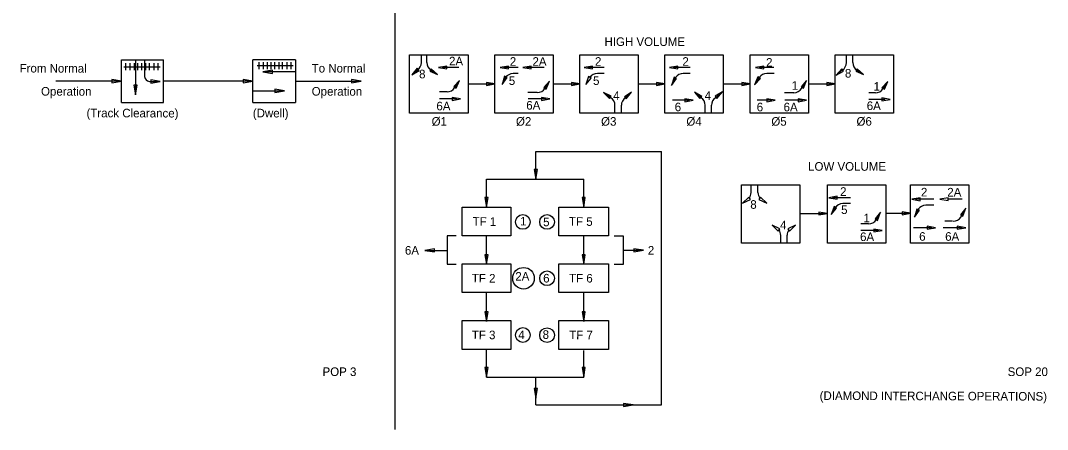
# Model space of a CAD drawing. Extents: x 10027 to 10797, y 10033 to 10528.
# Drawn here: x 10347 to 10765.1, y 10033.4 to 10199.9 of the extents above; entities that cross this region are included whole.
import ezdxf

# ---------------------------------------------------------------- set-up
doc = ezdxf.new("R2010")
doc.units = 0
for name, color, linetype in [('AdhocPoint_dp', 7, 'Continuous'), ('Default', 7, 'Continuous'), ('Dimension', 7, 'Continuous'), ('DSIndex', 7, 'Continuous'), ('SupstrConc', 7, 'Continuous')]:
    doc.layers.add(name, color=color, linetype=linetype)

msp = doc.modelspace()

# ---------------------------------------------------------------- linework, layer by layer
at = {"layer": 'AdhocPoint_dp'}
msp.add_line((10499.47, 10033.43), (10499.47, 10528.43), dxfattribs=at)
at = {"layer": 'Default'}
for p, q in [((10510.17, 10182.8), (10510.17, 10185.91)), ((10512.33, 10182.8), (10512.33, 10185.91)), ((10683.2, 10182.75), (10683.2, 10185.9)), ((10685.82, 10182.75), (10685.82, 10185.91)), ((10388.02, 10166.55), (10388.02, 10183.94)), ((10388.02, 10183.94), (10405.14, 10183.94)), ((10389.89, 10179.66), (10389.89, 10182.56)), ((10391.65, 10179.66), (10391.65, 10182.56)), ((10393.33, 10179.66), (10393.33, 10182.56)), ((10393.81, 10183.94), (10393.81, 10169.64)), ((10394.77, 10179.66), (10394.77, 10182.56)), ((10396.33, 10179.66), (10396.33, 10182.56)), ((10397.45, 10183.94), (10397.45, 10177.04)), ((10397.99, 10179.66), (10397.99, 10182.56)), ((10399.43, 10179.66), (10399.43, 10182.56)), ((10401.31, 10179.66), (10401.31, 10182.56)), ((10402.98, 10179.66), (10402.98, 10182.56)), ((10405.14, 10166.55), (10405.14, 10183.94)), ((10458.95, 10183.94), (10441.55, 10183.94)), ((10441.55, 10166.55), (10441.55, 10183.94)), ((10443.28, 10181.53), (10457.98, 10181.53)), ((10444.12, 10180.11), (10444.12, 10183)), ((10445.88, 10180.11), (10445.88, 10183)), ((10447.55, 10180.11), (10447.55, 10183)), ((10449, 10180.11), (10449, 10183)), ((10450.56, 10180.11), (10450.56, 10183)), ((10452.21, 10180.11), (10452.21, 10183)), ((10453.66, 10180.11), (10453.66, 10183)), ((10455.54, 10180.11), (10455.54, 10183)), ((10457.21, 10180.11), (10457.21, 10183)), ((10458.95, 10183.94), (10458.95, 10166.55)), ((10389.05, 10181.09), (10403.75, 10181.09)), ((10458.92, 10179.04), (10445.59, 10179.04)), ((10525.44, 10180.74), (10518.6, 10180.74)), ((10549.62, 10180.74), (10543.66, 10180.74)), ((10549.55, 10178.29), (10547.5, 10178.29)), ((10560.21, 10180.75), (10552.88, 10180.75)), ((10584.6, 10180.75), (10577.86, 10180.75)), ((10584.6, 10178.32), (10581.83, 10178.32)), ((10619.55, 10180.75), (10612.68, 10180.75)), ((10653.68, 10180.75), (10647.67, 10180.75)), ((10388.02, 10175.24), (10361.28, 10175.24)), ((10399.41, 10175.07), (10403.85, 10175.07)), ((10441.55, 10175.24), (10405.14, 10175.24)), ((10458.95, 10175.24), (10485.64, 10175.24)), ((10529.15, 10174.06), (10540.04, 10174.06)), ((10563.8, 10174.06), (10574.7, 10174.06)), ((10598.46, 10174.06), (10609.35, 10174.06)), ((10633.11, 10174.06), (10644.01, 10174.06)), ((10667.77, 10174.06), (10678.66, 10174.06)), ((10441.55, 10171.21), (10454.37, 10171.21)), ((10661.84, 10170.51), (10658.06, 10170.51)), ((10695.01, 10170.46), (10692.39, 10170.46)), ((10388.02, 10166.55), (10405.14, 10166.55)), ((10441.55, 10166.55), (10458.95, 10166.55)), ((10524.65, 10167.97), (10517.59, 10167.97)), ((10561, 10167.97), (10553.6, 10167.97)), ((10588.98, 10162.22), (10588.98, 10165.37)), ((10591.6, 10162.22), (10591.6, 10165.37)), ((10618.31, 10167.41), (10612.36, 10167.41)), ((10625.7, 10162.22), (10625.7, 10165.37)), ((10628.32, 10162.22), (10628.32, 10165.37)), ((10652.81, 10167.41), (10646.85, 10167.41)), ((10665.49, 10167.4), (10658.13, 10167.4)), ((10698.97, 10167.8), (10692.4, 10167.8)), ((10556.73, 10135.27), (10556.73, 10146.6)), ((10556.73, 10146.6), (10607.88, 10146.6)), ((10607.88, 10043.39), (10607.88, 10146.6)), ((10536.7, 10135.27), (10576.25, 10135.27)), ((10536.7, 10123.95), (10536.7, 10135.27)), ((10576.25, 10123.95), (10576.25, 10135.27)), ((10644.42, 10129.83), (10644.42, 10132.99)), ((10647.22, 10129.82), (10647.22, 10132.98)), ((10684.92, 10127.77), (10677.52, 10127.77)), ((10684.91, 10125.35), (10681.75, 10125.35)), ((10718.76, 10127.11), (10711.31, 10127.11)), ((10730.34, 10127.12), (10724.39, 10127.12)), ((10664.31, 10121.34), (10675.46, 10121.34)), ((10699.22, 10121.41), (10709.34, 10121.41)), ((10692.24, 10117.09), (10689.08, 10117.09)), ((10718, 10115.54), (10710.56, 10115.54)), ((10730.34, 10115.54), (10722.67, 10115.54)), ((10536.7, 10100.87), (10536.7, 10112.19)), ((10576.25, 10100.87), (10576.25, 10112.19)), ((10656.49, 10109.28), (10656.49, 10112.44)), ((10659.09, 10109.29), (10659.09, 10112.45)), ((10696.37, 10114.42), (10689.11, 10114.42)), ((10511.58, 10106.33), (10520.63, 10106.33)), ((10592.36, 10106.35), (10600.59, 10106.35)), ((10536.7, 10077.79), (10536.7, 10089.11)), ((10576.25, 10077.79), (10576.25, 10089.11)), ((10536.7, 10054.71), (10536.7, 10066.03)), ((10576.25, 10054.71), (10576.25, 10065.6)), ((10536.7, 10054.71), (10576.25, 10054.71)), ((10556.73, 10043.39), (10556.73, 10054.71)), ((10556.73, 10043.39), (10607.88, 10043.39))]:
    msp.add_line(p, q, dxfattribs=at)
for centre, radius, start, end in [((10506.39, 10182.82), 3.78, 304.2835, 359.6758), ((10516.12, 10182.83), 3.78, 180.3242, 235.7165), ((10679.43, 10182.77), 3.78, 304.2835, 359.6758), ((10689.6, 10182.77), 3.78, 180.3242, 235.7165), ((10547.52, 10174.51), 3.78, 90.3242, 145.7165), ((10581.84, 10174.54), 3.78, 90.3242, 145.7165), ((10399.61, 10177.23), 2.17, 185.1228, 264.5013), ((10661.82, 10174.29), 3.78, 270.3242, 325.7165), ((10695, 10174.25), 3.78, 270.3242, 325.7165), ((10585.21, 10165.36), 3.78, 0.3242, 55.7165), ((10595.38, 10165.35), 3.78, 124.2835, 179.6758), ((10621.92, 10165.36), 3.78, 0.3242, 55.7165), ((10632.1, 10165.36), 3.78, 124.2835, 179.6758), ((10640.64, 10129.85), 3.78, 323.8272, 359.6758), ((10650.99, 10129.84), 3.78, 180.3242, 217.1963), ((10681.78, 10121.57), 3.78, 90.3242, 145.7165), ((10692.22, 10120.87), 3.78, 270.3242, 325.7165), ((10652.71, 10112.42), 3.78, 0.3242, 35.4148), ((10662.87, 10112.44), 3.78, 145.5087, 179.6758)]:
    msp.add_arc(centre, radius, start, end, dxfattribs=at)
at = {"layer": 'Dimension'}
for p, q in [((10508.52, 10179.7), (10507.37, 10178.75)), ((10513.99, 10179.71), (10515.54, 10178.75)), ((10619.63, 10178.34), (10616.86, 10178.34)), ((10653.76, 10178.33), (10650.99, 10178.33)), ((10681.55, 10179.64), (10680.2, 10178.57)), ((10687.47, 10179.65), (10689.02, 10178.66)), ((10523.71, 10172.51), (10524.9, 10174.25)), ((10544.4, 10176.64), (10543.69, 10175.16)), ((10560.49, 10172.24), (10561.59, 10173.92)), ((10613.7, 10176.68), (10612.71, 10174.87)), ((10647.75, 10176.68), (10646.66, 10174.97)), ((10664.94, 10172.17), (10666.14, 10174.09)), ((10698.13, 10172.12), (10699.25, 10173.87)), ((10520.61, 10170.86), (10517.6, 10170.86)), ((10557.32, 10170.59), (10553.54, 10170.59)), ((10587.33, 10168.48), (10585.58, 10169.7)), ((10593.25, 10168.47), (10594.67, 10169.77)), ((10624.05, 10168.48), (10622.48, 10169.84)), ((10629.97, 10168.48), (10631.63, 10169.88)), ((10618.31, 10167.41), (10619.34, 10167.41)), ((10678.66, 10123.69), (10677.77, 10122.16)), ((10712.48, 10123.04), (10711.61, 10121.15)), ((10718.77, 10124.69), (10715.62, 10124.69)), ((10695.34, 10118.74), (10696.34, 10120.54)), ((10729.81, 10119.86), (10731.08, 10122.12)), ((10726.46, 10118.21), (10723.31, 10118.21))]:
    msp.add_line(p, q, dxfattribs=at)
for centre, radius in [((10551.47, 10117.91), 3), ((10561.35, 10117.91), 3), ((10551.76, 10094.98), 4.39), ((10561.36, 10094.96), 3), ((10551.49, 10071.87), 3), ((10561.36, 10071.81), 3)]:
    msp.add_circle(centre, radius, dxfattribs=at)
for centre, start, end in [((10616.82, 10174.56), 90.3242, 145.7165), ((10650.87, 10174.55), 90.3242, 145.7165), ((10520.59, 10174.64), 270.3242, 325.7165), ((10557.37, 10174.37), 270.3242, 325.7165), ((10715.61, 10120.91), 90.3242, 145.7165), ((10726.69, 10121.99), 270.3242, 325.7165)]:
    msp.add_arc(centre, 3.78, start, end, dxfattribs=at)
at = {"layer": 'DSIndex'}
for points in [[(10505.39, 10185.91), (10529.15, 10185.91), (10529.15, 10162.22), (10505.39, 10162.22)], [(10540.04, 10185.91), (10563.8, 10185.91), (10563.8, 10162.22), (10540.04, 10162.22)], [(10574.7, 10185.91), (10598.46, 10185.91), (10598.46, 10162.22), (10574.7, 10162.22)], [(10609.35, 10185.91), (10633.11, 10185.91), (10633.11, 10162.22), (10609.35, 10162.22)], [(10644.01, 10185.91), (10667.77, 10185.91), (10667.77, 10162.22), (10644.01, 10162.22)], [(10678.66, 10185.91), (10702.42, 10185.91), (10702.42, 10162.22), (10678.66, 10162.22)], [(10640.55, 10132.99), (10664.31, 10132.99), (10664.31, 10109.29), (10640.55, 10109.29)], [(10675.46, 10132.99), (10699.22, 10132.99), (10699.22, 10109.29), (10675.46, 10109.29)], [(10709.34, 10132.99), (10733.1, 10132.99), (10733.1, 10109.29), (10709.34, 10109.29)], [(10526.8, 10123.95), (10546.54, 10123.95), (10546.54, 10112.19), (10526.8, 10112.19)], [(10566.15, 10123.95), (10586.34, 10123.95), (10586.34, 10112.19), (10566.15, 10112.19)], [(10526.8, 10100.87), (10546.54, 10100.87), (10546.54, 10089.11), (10526.8, 10089.11)], [(10566.15, 10100.87), (10586.34, 10100.87), (10586.34, 10089.11), (10566.15, 10089.11)], [(10526.8, 10077.79), (10546.54, 10077.79), (10546.54, 10066.03), (10526.8, 10066.03)], [(10566.15, 10077.79), (10586.34, 10077.79), (10586.34, 10066.03), (10566.15, 10066.03)]]:
    msp.add_lwpolyline(points, close=True, dxfattribs=at)
for points in [[(10524.31, 10112.19), (10520.7, 10112.19), (10520.7, 10100.66), (10524.31, 10100.66)], [(10588.67, 10112.18), (10592.28, 10112.18), (10592.28, 10100.57), (10588.67, 10100.57)]]:
    msp.add_lwpolyline(points, dxfattribs=at)
at = {"layer": 'SupstrConc'}
for points in [[(10445.59, 10179.04), (10449.5, 10178.38), (10449.5, 10179.7)], [(10506.25, 10177.81), (10509.25, 10179.55), (10508.51, 10180.44)], [(10516.78, 10177.98), (10514.18, 10180.27), (10513.57, 10179.28)], [(10517.14, 10180.74), (10520.55, 10180.16), (10520.55, 10181.32)], [(10542.19, 10180.74), (10545.61, 10180.16), (10545.61, 10181.32)], [(10551.41, 10180.75), (10554.83, 10180.17), (10554.83, 10181.33)], [(10576.44, 10180.75), (10579.85, 10180.18), (10579.85, 10181.33)], [(10611.22, 10180.75), (10614.63, 10180.17), (10614.63, 10181.33)], [(10646.2, 10180.75), (10649.62, 10180.17), (10649.62, 10181.33)], [(10679.05, 10177.66), (10682.09, 10179.33), (10681.37, 10180.24)], [(10690.19, 10177.91), (10687.62, 10180.24), (10687, 10179.27)], [(10388.02, 10175.24), (10384.11, 10175.91), (10384.11, 10174.58)], [(10393.81, 10169.64), (10394.47, 10173.54), (10393.15, 10173.54)], [(10403.85, 10175.07), (10399.94, 10175.73), (10399.94, 10174.41)], [(10441.55, 10175.24), (10437.65, 10175.91), (10437.65, 10174.58)], [(10485.64, 10175.24), (10481.74, 10175.91), (10481.74, 10174.58)], [(10525.73, 10175.46), (10523.32, 10172.97), (10524.28, 10172.31)], [(10540.04, 10174.06), (10536.63, 10174.64), (10536.63, 10173.48)], [(10543.06, 10173.83), (10545.05, 10176.67), (10544.01, 10177.17)], [(10562.4, 10175.17), (10560.05, 10172.63), (10561.02, 10171.99)], [(10574.7, 10174.06), (10571.28, 10174.64), (10571.28, 10173.48)], [(10577.09, 10173.8), (10579.28, 10176.49), (10578.28, 10177.06)], [(10609.35, 10174.06), (10605.94, 10174.64), (10605.94, 10173.48)], [(10611.97, 10173.5), (10614.11, 10176.23), (10613.1, 10176.78)], [(10644.01, 10174.06), (10640.59, 10174.64), (10640.59, 10173.48)], [(10645.87, 10173.74), (10648.2, 10176.3), (10647.22, 10176.92)], [(10667.04, 10175.54), (10664.74, 10172.94), (10665.72, 10172.33)], [(10678.66, 10174.06), (10675.24, 10174.64), (10675.24, 10173.48)], [(10700.05, 10175.1), (10697.71, 10172.54), (10698.68, 10171.92)], [(10454.37, 10171.21), (10450.46, 10171.88), (10450.46, 10170.55)], [(10584.27, 10170.62), (10586.74, 10168.19), (10587.4, 10169.13)], [(10595.74, 10170.74), (10592.82, 10168.87), (10593.6, 10168.01)], [(10621.41, 10170.76), (10623.61, 10168.08), (10624.37, 10168.96)], [(10632.75, 10170.81), (10629.76, 10169.06), (10630.5, 10168.18)], [(10526.11, 10167.97), (10522.7, 10168.55), (10522.7, 10167.39)], [(10562.47, 10167.96), (10559.06, 10168.54), (10559.06, 10167.39)], [(10620.81, 10167.41), (10617.39, 10167.99), (10617.39, 10166.83)], [(10654.27, 10167.41), (10650.86, 10167.99), (10650.86, 10166.83)], [(10666.95, 10167.4), (10663.54, 10167.98), (10663.54, 10166.82)], [(10701.09, 10167.8), (10697.67, 10168.37), (10697.67, 10167.22)], [(10556.73, 10135.27), (10557.39, 10139.18), (10556.06, 10139.18)], [(10536.7, 10123.95), (10537.36, 10127.85), (10536.04, 10127.85)], [(10576.25, 10123.95), (10576.92, 10127.85), (10575.59, 10127.85)], [(10640.96, 10125.57), (10644.11, 10127.01), (10643.46, 10127.97)], [(10650.78, 10125.59), (10648.28, 10128), (10647.63, 10127.04)], [(10676.06, 10127.77), (10679.48, 10127.19), (10679.48, 10128.35)], [(10709.85, 10127.11), (10713.26, 10126.53), (10713.26, 10127.69)], [(10721.21, 10127.15), (10724.63, 10126.58), (10724.63, 10127.73)], [(10676.98, 10120.89), (10679.2, 10123.56), (10678.2, 10124.14)], [(10711, 10119.82), (10712.96, 10122.68), (10711.91, 10123.16)], [(10731.82, 10123.49), (10729.65, 10120.79), (10730.66, 10120.23)], [(10675.46, 10121.34), (10672.04, 10121.92), (10672.04, 10120.76)], [(10697.06, 10121.81), (10694.88, 10119.12), (10695.89, 10118.55)], [(10709.34, 10121.41), (10705.92, 10121.99), (10705.92, 10120.83)], [(10652.99, 10116.57), (10655.49, 10114.17), (10656.14, 10115.12)], [(10662.55, 10116.55), (10659.4, 10115.1), (10660.05, 10114.15)], [(10697.84, 10114.42), (10694.42, 10115), (10694.42, 10113.84)], [(10719.47, 10115.54), (10716.05, 10116.12), (10716.05, 10114.96)], [(10731.8, 10115.54), (10728.39, 10116.12), (10728.39, 10114.96)], [(10511.58, 10106.33), (10515.48, 10105.67), (10515.48, 10106.99)], [(10600.59, 10106.35), (10596.69, 10107.01), (10596.69, 10105.69)], [(10536.7, 10100.66), (10537.36, 10104.56), (10536.04, 10104.56)], [(10576.25, 10100.66), (10576.92, 10104.56), (10575.59, 10104.56)], [(10536.7, 10077.36), (10537.36, 10081.26), (10536.04, 10081.26)], [(10576.25, 10077.36), (10576.92, 10081.26), (10575.59, 10081.26)], [(10536.7, 10054.71), (10537.36, 10058.61), (10536.04, 10058.61)], [(10576.25, 10054.71), (10576.92, 10058.61), (10575.59, 10058.61)], [(10556.73, 10046.15), (10557.39, 10050.06), (10556.06, 10050.06)], [(10596.34, 10043.39), (10592.44, 10044.05), (10592.44, 10042.72)]]:
    msp.add_lwpolyline(points, close=True, dxfattribs=at)

# ---------------------------------------------------------------- texts
at = {"layer": 'Dimension'}
for s, p in [('HIGH VOLUME', (10584.73, 10189.53)), ('2A', (10521.43, 10181.61)), ('2', (10546.18, 10181.46)), ('2A', (10555.41, 10181.46)), ('2', (10580.85, 10181.46)), ('2', (10616.44, 10181.45)), ('2', (10650.52, 10181.1)), ('8', (10509.23, 10176.35)), ('8', (10682.63, 10176.67)), ('5', (10545.75, 10173.66)), ('5', (10580.06, 10173.66)), ('1', (10660.94, 10171.69)), ('1', (10694.3, 10171.32)), ('4', (10588.26, 10167.59)), ('4', (10625.51, 10167.59)), ('6A', (10516.28, 10163.32)), ('6A', (10552.87, 10163.62)), ('6', (10613.32, 10162.95)), ('6', (10646.71, 10162.92)), ('6A', (10657.65, 10162.92)), ('6A', (10691.51, 10163.45)), ('Ø1', (10514.34, 10157.07)), ('Ø2', (10548.68, 10157.07)), ('Ø3', (10583.34, 10157.07)), ('Ø4', (10618.06, 10157.07)), ('Ø5', (10652.66, 10157.07)), ('Ø6', (10687.34, 10157.07)), ('LOW VOLUME', (10667.63, 10138.74)), ('2', (10680.67, 10128.52)), ('2', (10713.57, 10128.27)), ('2A', (10724.29, 10128.25)), ('8', (10644.09, 10123.25)), ('5', (10681.07, 10121.12)), ('1', (10690.17, 10117.74)), ('4', (10656.18, 10114.86)), ('6A', (10688.79, 10110.12)), ('6', (10712.85, 10110.24)), ('6A', (10723.43, 10110.23)), ('6A', (10503.46, 10104.58)), ('2A', (10548.41, 10094)), ('SOP 20', (10748.88, 10055.18))]:
    msp.add_text(s, height=3.5, dxfattribs=at).set_placement(p)
for s, rotation, p in [('From Normal', 359.8217, (10346.57, 10178.74)), ('To Normal', 359.8217, (10465.5, 10178.73)), ('Operation', 359.8217, (10355.29, 10169.33)), ('Operation', 359.8217, (10465.5, 10169.33)), ('(Track Clearance)', 359.8217, (10373.81, 10160.52)), ('(Dwell)', 359.8217, (10441.52, 10160.47)), ('TF 1', 359.6902, (10531.01, 10116.35)), ('1', 359.6943, (10550.39, 10116.48)), ('5', 359.6943, (10559.72, 10116.17)), ('TF 5', 359.6902, (10570.28, 10116.35)), ('2', 359.6943, (10602.37, 10104.61)), ('TF 2', 359.6902, (10530.69, 10093.27)), ('6', 359.6943, (10559.74, 10093.26)), ('TF 6', 359.6902, (10570.3, 10093.27)), ('TF 3', 359.6902, (10530.69, 10070.19)), ('4', 359.6943, (10549.6, 10070.2)), ('8', 359.6943, (10559.53, 10070.3)), ('TF 7', 359.6902, (10570.35, 10070.19)), ('POP 3', 359.8217, (10469.92, 10055.21)), ('(DIAMOND INTERCHANGE OPERATIONS)', 359.8217, (10672.33, 10045.44))]:
    msp.add_text(s, height=3.5, rotation=rotation, dxfattribs=at).set_placement(p)

doc.saveas('drawing.dxf')
